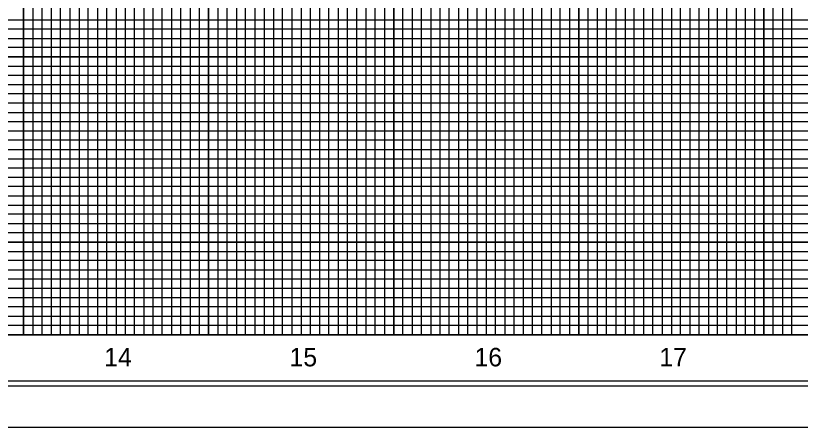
# Model space of a CAD drawing. Extents: x 572694 to 574378, y -52955 to -51855.
# Drawn here: x 573257.3 to 573681.2, y -52955.1 to -52732.9 of the extents above; entities that cross this region are included whole.
import ezdxf

# ---------------------------------------------------------------- set-up
doc = ezdxf.new("R2010")
doc.units = 0
for name, color, linetype in [('Exist Profile Cell', 7, 'Continuous'), ('Exist Vertical Profile Horizontal Axis Label Major', 7, 'Continuous'), ('Sheet Cutting Line CELL', 7, 'Continuous'), ('Sheet DOT Grid CELL', 7, 'Continuous'), ('Sheet Plot Border Inside CELL', 7, 'Continuous'), ('Sheet Plot Border Outside CELL', 7, 'Continuous'), ('Sheet Profile CELL', 7, 'Continuous'), ('Sheet Profile Grid Major CELL', 7, 'Continuous'), ('Sheet Profile Grid Middle CELL', 7, 'Continuous'), ('Sheet Profile Grid Minor CELL', 7, 'Continuous')]:
    doc.layers.add(name, color=color, linetype=linetype)

msp = doc.modelspace()

# ---------------------------------------------------------------- linework, layer by layer
at = {"layer": 'Exist Profile Cell'}
msp.add_line((572911.5, -52905.14), (574213.46, -52905.14), dxfattribs=at)
at = {"layer": 'Sheet Cutting Line CELL'}
msp.add_line((572694.5, -52955.14), (574378.5, -52955.14), dxfattribs=at)
at = {"layer": 'Sheet DOT Grid CELL'}
for p, q in [((573261.5, -51880.14), (573261.5, -52905.14)), ((573311.5, -51880.14), (573311.5, -52905.14)), ((573361.5, -51880.14), (573361.5, -52905.14)), ((573411.5, -51880.14), (573411.5, -52905.14)), ((573461.5, -51880.14), (573461.5, -52905.14)), ((573511.5, -51880.14), (573511.5, -52905.14)), ((573561.5, -51880.14), (573561.5, -52905.14)), ((573611.5, -51880.14), (573611.5, -52905.14)), ((573661.5, -51880.14), (573661.5, -52905.14)), ((572861.5, -52755.14), (574361.5, -52755.14)), ((572861.5, -52805.14), (574361.5, -52805.14)), ((572861.5, -52855.14), (574361.5, -52855.14))]:
    msp.add_line(p, q, dxfattribs=at)
at = {"layer": 'Sheet Plot Border Inside CELL'}
msp.add_lwpolyline([(574374, -51877.59), (572707.5, -51877.59), (572707.5, -52932.69), (574374, -52932.69)], close=True, dxfattribs=at)
at = {"layer": 'Sheet Plot Border Outside CELL'}
msp.add_lwpolyline([(574378.5, -51855.14), (572694.5, -51855.14), (572694.5, -52955.14), (574378.5, -52955.14)], close=True, dxfattribs=at)
at = {"layer": 'Sheet Profile CELL'}
msp.add_line((574361.5, -52905.14), (572861.5, -52905.14), dxfattribs=at)
msp.add_lwpolyline([(574361.5, -51880.14), (572861.5, -51880.14), (572861.5, -52930.14), (574361.5, -52930.14)], close=True, dxfattribs=at)
at = {"layer": 'Sheet Profile Grid Major CELL'}
for points in [[(573211.5, -52905.14), (573261.5, -52905.14), (573261.5, -51880.14)], [(573311.5, -51880.14), (573311.5, -52905.14), (573361.5, -52905.14), (573361.5, -51880.14)], [(573411.5, -51880.14), (573411.5, -52905.14), (573461.5, -52905.14), (573461.5, -51880.14)], [(573511.5, -51880.14), (573511.5, -52905.14), (573561.5, -52905.14), (573561.5, -51880.14)], [(573611.5, -51880.14), (573611.5, -52905.14), (573661.5, -52905.14), (573661.5, -51880.14)], [(574361.5, -52755.14), (572861.5, -52755.14), (572861.5, -52705.14), (574361.5, -52705.14)], [(574361.5, -52855.14), (572861.5, -52855.14), (572861.5, -52805.14), (574361.5, -52805.14)]]:
    msp.add_lwpolyline(points, dxfattribs=at)
at = {"layer": 'Sheet Profile Grid Middle CELL'}
for points in [[(573286.5, -51880.14), (573286.5, -52905.14), (573336.5, -52905.14), (573336.5, -51880.14)], [(573386.5, -51880.14), (573386.5, -52905.14), (573436.5, -52905.14), (573436.5, -51880.14)], [(573486.5, -51880.14), (573486.5, -52905.14), (573536.5, -52905.14), (573536.5, -51880.14)], [(573586.5, -51880.14), (573586.5, -52905.14), (573636.5, -52905.14), (573636.5, -51880.14)], [(574361.5, -52780.14), (572861.5, -52780.14), (572861.5, -52830.14), (574361.5, -52830.14)], [(574361.5, -52880.14), (572861.5, -52880.14)]]:
    msp.add_lwpolyline(points, dxfattribs=at)
at = {"layer": 'Sheet Profile Grid Minor CELL'}
for points in [[(573266.5, -51880.14), (573266.5, -52905.14), (573271.5, -52905.14), (573271.5, -51880.14)], [(573276.5, -51880.14), (573276.5, -52905.14), (573281.5, -52905.14), (573281.5, -51880.14)], [(573291.5, -51880.14), (573291.5, -52905.14), (573296.5, -52905.14), (573296.5, -51880.14)], [(573301.5, -51880.14), (573301.5, -52905.14), (573306.5, -52905.14), (573306.5, -51880.14)], [(573316.5, -51880.14), (573316.5, -52905.14), (573321.5, -52905.14), (573321.5, -51880.14)], [(573326.5, -51880.14), (573326.5, -52905.14), (573331.5, -52905.14), (573331.5, -51880.14)], [(573341.5, -51880.14), (573341.5, -52905.14), (573346.5, -52905.14), (573346.5, -51880.14)], [(573351.5, -51880.14), (573351.5, -52905.14), (573356.5, -52905.14), (573356.5, -51880.14)], [(573366.5, -51880.14), (573366.5, -52905.14), (573371.5, -52905.14), (573371.5, -51880.14)], [(573376.5, -51880.14), (573376.5, -52905.14), (573381.5, -52905.14), (573381.5, -51880.14)], [(573391.5, -51880.14), (573391.5, -52905.14)], [(573396.5, -51880.14), (573396.5, -52905.14), (573401.5, -52905.14), (573401.5, -51880.14), (573406.5, -51880.14), (573406.5, -52905.14), (573416.5, -52905.14), (573416.5, -51880.14), (573421.5, -51880.14), (573421.5, -52905.14), (573426.5, -52905.14), (573426.5, -51880.14), (573431.5, -51880.14), (573431.5, -52905.14)], [(573441.5, -52905.14), (573441.5, -51880.14)], [(573446.5, -51880.14), (573446.5, -52905.14), (573451.5, -52905.14), (573451.5, -51880.14)], [(573456.5, -51880.14), (573456.5, -52905.14), (573466.5, -52905.14), (573466.5, -51880.14)], [(573471.5, -51880.14), (573471.5, -52905.14), (573471.5, -52905.14), (573476.5, -52905.14), (573476.5, -51880.14)], [(573481.5, -51880.14), (573481.5, -52905.14), (573491.5, -52905.14), (573491.5, -51880.14)], [(573496.5, -51880.14), (573496.5, -52905.14), (573501.5, -52905.14), (573501.5, -51880.14)], [(573506.5, -51880.14), (573506.5, -52905.14), (573516.5, -52905.14), (573516.5, -51880.14)], [(573521.5, -51880.14), (573521.5, -52905.14), (573526.5, -52905.14), (573526.5, -51880.14)], [(573531.5, -51880.14), (573531.5, -52905.14), (573541.5, -52905.14), (573541.5, -51880.14)], [(573546.5, -51880.14), (573546.5, -52905.14), (573551.5, -52905.14), (573551.5, -51880.14)], [(573556.5, -51880.14), (573556.5, -52905.14), (573566.5, -52905.14), (573566.5, -51880.14)], [(573571.5, -51880.14), (573571.5, -52905.14), (573576.5, -52905.14), (573576.5, -51880.14)], [(573581.5, -51880.14), (573581.5, -52905.14), (573591.5, -52905.14), (573591.5, -51880.14)], [(573596.5, -51880.14), (573596.5, -52905.14), (573601.5, -52905.14), (573601.5, -51880.14)], [(573606.5, -51880.14), (573606.5, -52905.14), (573616.5, -52905.14), (573616.5, -51880.14)], [(573621.5, -51880.14), (573621.5, -52905.14)], [(573621.5, -52905.14), (573626.5, -52905.14), (573626.5, -51880.74)], [(573631.5, -51880.74), (573631.5, -52905.14), (573641.5, -52905.14), (573641.5, -51880.14)], [(573646.5, -51880.14), (573646.5, -52905.14), (573651.5, -52905.14), (573651.5, -51880.14)], [(573656.5, -51880.14), (573656.5, -52905.14), (573666.5, -52905.14), (573666.5, -51880.14)], [(573671.5, -51880.14), (573671.5, -52905.14), (573676.5, -52905.14), (573676.5, -51880.14)], [(572911.5, -52735.14), (574311.5, -52735.14)], [(574311.5, -52740.14), (572911.5, -52740.14), (572911.5, -52745.14), (574311.5, -52745.14)], [(574311.5, -52750.14), (572911.5, -52750.14), (572911.5, -52760.14), (574311.5, -52760.14)], [(574311.5, -52765.14), (572911.5, -52765.14), (572911.5, -52770.14), (574311.5, -52770.14)], [(574311.5, -52775.14), (572911.5, -52775.14), (572911.5, -52785.14), (574311.5, -52785.14)], [(574311.5, -52790.14), (572911.5, -52790.14), (572911.5, -52795.14), (574311.5, -52795.14)], [(574311.5, -52800.14), (572911.5, -52800.14), (572911.5, -52810.14), (574311.5, -52810.14)], [(574311.5, -52815.14), (572911.5, -52815.14), (572911.5, -52820.14), (574311.5, -52820.14)], [(574311.5, -52825.14), (572911.5, -52825.14), (572911.5, -52835.14), (574311.5, -52835.14)], [(574311.5, -52840.14), (572911.5, -52840.14), (572911.5, -52845.14), (574311.5, -52845.14)], [(574311.5, -52850.14), (572911.5, -52850.14), (572911.5, -52860.14), (574311.5, -52860.14)], [(574311.5, -52865.14), (572911.5, -52865.14), (572911.5, -52870.14), (574311.5, -52870.14)], [(574311.5, -52875.14), (572911.5, -52875.14), (572911.5, -52885.14), (574311.5, -52885.14)], [(574311.5, -52890.14), (572911.5, -52890.14), (572911.5, -52895.14), (574311.5, -52895.14)], [(574311.5, -52900.14), (572911.5, -52900.14)]]:
    msp.add_lwpolyline(points, dxfattribs=at)

# ---------------------------------------------------------------- texts
at = {"layer": 'Exist Vertical Profile Horizontal Axis Label Major'}
for s, p in [('14', (573305.14, -52922.24)), ('15', (573405.24, -52922.24)), ('16', (573505.18, -52922.24)), ('17', (573605.03, -52922.24))]:
    msp.add_text(s, height=10, dxfattribs=at).set_placement(p)

doc.saveas('drawing.dxf')
